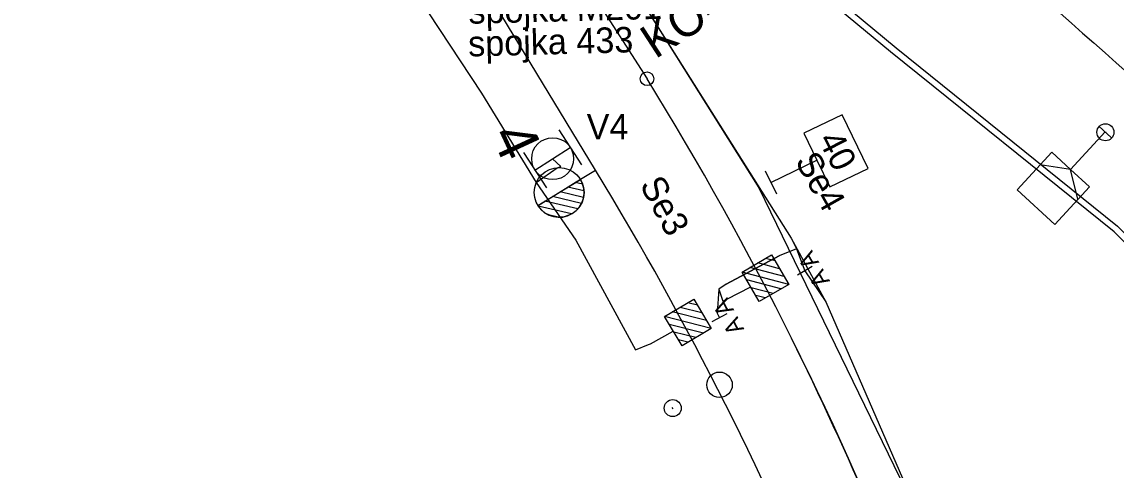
# Model space of a CAD drawing. Extents: x -496570 to -495506, y -1089156 to -1088046.
# Drawn here: x -495875.3 to -495811, y -1088785.1 to -1088758.8 of the extents above; entities that cross this region are included whole.
import ezdxf

# ---------------------------------------------------------------- set-up
doc = ezdxf.new("R2010")
doc.units = 0
for name, color, linetype in [('11', 7, 'Continuous'), ('14', 7, 'Continuous'), ('15', 7, 'Continuous'), ('20', 7, 'Continuous'), ('27', 7, 'Continuous'), ('4', 7, 'Continuous'), ('54', 7, 'Continuous'), ('PŮVODNÍ_NÁVRH', 7, 'Continuous'), ('SEE', 7, 'Continuous')]:
    doc.layers.add(name, color=color, linetype=linetype)

msp = doc.modelspace()

# ---------------------------------------------------------------- linework, layer by layer
at = {"layer": '11'}
for p, q in [((-495813.67, -1088767.458), (-495811.645, -1088765.244)), ((-495811.276, -1088765.581), (-495812.014, -1088764.907)), ((-495811.672, -1088765.277), (-495811.572, -1088765.277)), ((-495837.007, -1088781.51), (-495837.081, -1088781.444))]:
    msp.add_line(p, q, dxfattribs=at)
for points in [[(-495813.67, -1088767.458), (-495814.777, -1088766.445), (-495816.802, -1088768.659), (-495814.588, -1088770.684), (-495812.563, -1088768.47), (-495813.67, -1088767.458)], [(-495813.239, -1088769.209), (-495813.67, -1088767.458), (-495815.453, -1088767.184)]]:
    msp.add_lwpolyline(points, dxfattribs=at)
for centre, radius in [((-495811.622, -1088765.277), 0.5), ((-495834.293, -1088780.107), 0.75), ((-495837.044, -1088781.477), 0.5)]:
    msp.add_circle(centre, radius, dxfattribs=at)
at = {"layer": '14'}
msp.add_line((-495841.879, -1088756.944), (-495838.553, -1088762.134), dxfattribs=at)
msp.add_circle((-495838.553, -1088762.134), 0.4, dxfattribs=at)
for centre, major_axis, ratio, start_param, end_param in [((-493580.338, -1086191.204), (6302.474, -5605.928), 0.403422, 4.716139, 4.719484), ((-496001.561, -1088862.9), (172.862, -82.791), 0.999809, 0.816932, 1.000419), ((-496005.523, -1088867.532), (161.864, 103.358), 0.999852, 6.098703, 6.262806), ((-496013.215, -1088868.04), (170.403, -112.896), 0.999722, 0.822263, 1.044914)]:
    msp.add_ellipse(centre, major_axis=major_axis, ratio=ratio, start_param=start_param, end_param=end_param, dxfattribs=at)
at = {"layer": '15'}
for p, q in [((-495843.734, -1088765.126), (-495842.396, -1088767.196)), ((-495845.804, -1088766.464), (-495844.466, -1088768.534)), ((-495845.135, -1088767.499), (-495843.065, -1088766.161)), ((-495830.762, -1088773.291), (-495832.046, -1088772.952)), ((-495831.029, -1088772.833), (-495831.588, -1088772.685)), ((-495830.228, -1088774.208), (-495832.963, -1088773.486)), ((-495830.495, -1088773.75), (-495832.505, -1088773.219)), ((-495830.686, -1088774.475), (-495832.696, -1088773.944)), ((-495831.145, -1088774.742), (-495832.429, -1088774.403)), ((-495831.603, -1088775.008), (-495832.163, -1088774.861)), ((-495835.324, -1088775.882), (-495836.612, -1088775.558)), ((-495835.596, -1088775.427), (-495836.156, -1088775.286)), ((-495834.78, -1088776.793), (-495837.523, -1088776.101)), ((-495835.052, -1088776.338), (-495837.068, -1088775.83)), ((-495835.235, -1088777.065), (-495837.251, -1088776.556)), ((-495835.691, -1088777.337), (-495836.979, -1088777.012)), ((-495836.146, -1088777.609), (-495836.707, -1088777.467))]:
    msp.add_line(p, q, dxfattribs=at)
for points in [[(-495831.957, -1088775.214), (-495832.963, -1088773.486), (-495831.235, -1088772.48), (-495830.228, -1088774.208)], [(-495831.957, -1088775.214), (-495832.963, -1088773.486), (-495831.235, -1088772.48), (-495830.228, -1088774.208)], [(-495836.497, -1088777.819), (-495837.523, -1088776.101), (-495835.805, -1088775.076), (-495834.78, -1088776.793)], [(-495836.497, -1088777.819), (-495837.523, -1088776.101), (-495835.805, -1088775.076), (-495834.78, -1088776.793)]]:
    msp.add_lwpolyline(points, close=True, dxfattribs=at)
for points in [[(-495831.957, -1088775.214), (-495832.963, -1088773.486), (-495831.235, -1088772.48), (-495830.228, -1088774.208), (-495831.957, -1088775.214)], [(-495831.957, -1088775.214), (-495832.963, -1088773.486), (-495831.235, -1088772.48), (-495830.228, -1088774.208), (-495831.957, -1088775.214)], [(-495836.497, -1088777.819), (-495837.523, -1088776.101), (-495835.805, -1088775.076), (-495834.78, -1088776.793), (-495836.497, -1088777.819)], [(-495836.497, -1088777.819), (-495837.523, -1088776.101), (-495835.805, -1088775.076), (-495834.78, -1088776.793), (-495836.497, -1088777.819)]]:
    msp.add_lwpolyline(points, dxfattribs=at)
msp.add_circle((-495844.097, -1088766.826), 1.232, dxfattribs=at)
at = {"layer": '20'}
for p, q in [((-495828.848, -1088773.159), (-495829.712, -1088773.661)), ((-495833.859, -1088775.944), (-495834.741, -1088776.416))]:
    msp.add_line(p, q, dxfattribs=at)
at = {"layer": '27'}
for p, q in [((-495844.963, -1088769.573), (-495842.47, -1088768.039)), ((-495844.955, -1088769.57), (-495842.462, -1088768.035)), ((-495842.461, -1088768.036), (-495841.587, -1088767.494)), ((-495842.259, -1088768.723), (-495843.214, -1088768.497)), ((-495842.338, -1088768.324), (-495842.768, -1088768.222)), ((-495842.622, -1088769.778), (-495844.551, -1088769.319)), ((-495842.404, -1088769.45), (-495844.105, -1088769.044)), ((-495842.286, -1088769.098), (-495843.659, -1088768.771)), ((-495844.963, -1088769.574), (-495844.963, -1088769.573)), ((-495842.987, -1088770.072), (-495844.94, -1088769.607)), ((-495843.765, -1088770.266), (-495844.34, -1088770.13))]:
    msp.add_line(p, q, dxfattribs=at)
msp.add_lwpolyline([(-495841.587, -1088767.494), (-495850.196, -1088753.283), (-495858.708, -1088739.233)], dxfattribs=at)
msp.add_circle((-495843.716, -1088768.806), 1.462, dxfattribs=at)
msp.add_arc((-495843.717, -1088768.806), 1.464, 211.63994, 31.60079, dxfattribs=at)
at = {"layer": '4'}
msp.add_line((-495831.602, -1088767.542), (-495830.95, -1088768.892), dxfattribs=at)
msp.add_lwpolyline([(-495831.276, -1088768.217), (-495828.575, -1088766.912), (-495827.813, -1088768.488), (-495825.562, -1088767.401), (-495827.084, -1088764.249), (-495829.336, -1088765.336), (-495828.575, -1088766.912)], dxfattribs=at)
at = {"layer": '54'}
for points in [[(-495791.286, -1088790.273), (-495804.369, -1088777.872), (-495811.106, -1088771.12), (-495824.244, -1088760.551), (-495840.179, -1088747.357), (-495841.548, -1088746.404), (-495845, -1088746.917), (-495854.533, -1088753.524), (-495860.828, -1088746.983), (-495869.129, -1088742.363), (-495894.734, -1088714.89), (-495907.733, -1088698.276), (-495926.154, -1088680.584), (-495936.743, -1088670.436), (-495952.112, -1088656.757)], [(-495951.647, -1088656.374), (-495945.893, -1088661.488), (-495936.346, -1088669.973), (-495925.773, -1088680.163), (-495906.553, -1088698.536), (-495896.884, -1088711.088), (-495893.995, -1088714.839), (-495868.155, -1088742.416), (-495860.018, -1088746.657), (-495854.533, -1088753.524), (-495845, -1088746.917), (-495841.548, -1088746.404), (-495840.19, -1088746.67), (-495839.894, -1088747.064), (-495839.734, -1088747.366), (-495839.482, -1088747.646), (-495839.66, -1088747.957), (-495839.679, -1088748.032), (-495838.294, -1088748.402), (-495823.909, -1088760.307), (-495810.91, -1088770.79), (-495804.093, -1088777.585), (-495801.02, -1088780.504), (-495790.99, -1088790.03)], [(-495845, -1088746.917), (-495844.436, -1088748.714), (-495843.517, -1088749.579), (-495843.46, -1088749.918), (-495843.602, -1088750.084), (-495830.082, -1088771.492), (-495829.77, -1088772.13), (-495829.28, -1088773.41), (-495828.053, -1088775.227), (-495820.013, -1088793.687), (-495819.345, -1088795.504)], [(-495854.533, -1088753.524), (-495854.79, -1088754.03), (-495851.4, -1088758.25), (-495848.28, -1088762.98), (-495845.07, -1088768.22), (-495842.74, -1088771.62), (-495839.22, -1088778.05), (-495838.46, -1088777.74), (-495838.34, -1088777.7), (-495837.01, -1088776.96)], [(-495845.07, -1088768.22), (-495843.83, -1088767.36), (-495843.62, -1088767.28), (-495844.1, -1088766.83)], [(-495829.77, -1088772.13), (-495830.78, -1088772.54), (-495833.91, -1088774.2), (-495834.34, -1088774.49), (-495834.09, -1088775.2), (-495833.87, -1088775.07), (-495832.46, -1088774.35)], [(-495834.34, -1088774.49), (-495834.43, -1088775.9), (-495834.3, -1088776.18)]]:
    msp.add_lwpolyline(points, dxfattribs=at)
at = {"layer": 'PŮVODNÍ_NÁVRH'}
for p, q in [((-495830.082, -1088771.492), (-495828.053, -1088775.227)), ((-495833.91, -1088774.2), (-495830.78, -1088772.54))]:
    msp.add_line(p, q, dxfattribs=at)
at = {"layer": 'SEE'}
msp.add_lwpolyline([(-495845, -1088746.917), (-495844.436, -1088748.714), (-495831.978, -1088768.541), (-495823.009, -1088786.973)], dxfattribs=at)

# ---------------------------------------------------------------- texts
at = {"layer": '14'}
msp.add_text('KO=ZP', height=2, rotation=33.0552, dxfattribs=at).set_placement((-495838.064, -1088761.001))
at = {"layer": '15'}
msp.add_text('V4', height=1.5, dxfattribs=at).set_placement((-495842.098, -1088765.697))
at = {"layer": '20'}
for s, height, rotation, p in [('Se4', 1.5, 299.55833, (-495829.889, -1088766.967)), ('Se3', 1.5, 298.27733, (-495839.009, -1088768.359)), ('  A A', 1, 120.16947, (-495827.416, -1088774.661)), ('  A A', 1, 118.18475, (-495832.48, -1088777.494))]:
    msp.add_text(s, height=height, rotation=rotation, dxfattribs=at).set_placement(p)
at = {"layer": '27'}
msp.add_text('4', height=2.5, rotation=294.82535, dxfattribs=at).set_placement((-495847.755, -1088765.439))
at = {"layer": '4'}
msp.add_text('40', height=1.5, rotation=297.15646, dxfattribs=at).set_placement((-495828.527, -1088765.698))
at = {"layer": '54'}
for s, p in [('spojka M201', (-495849.029, -1088758.904)), ('spojka 433', (-495849.042, -1088760.825))]:
    msp.add_text(s, height=1.5, rotation=1.47691, dxfattribs=at).set_placement(p)

doc.saveas('drawing.dxf')
